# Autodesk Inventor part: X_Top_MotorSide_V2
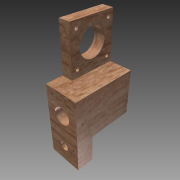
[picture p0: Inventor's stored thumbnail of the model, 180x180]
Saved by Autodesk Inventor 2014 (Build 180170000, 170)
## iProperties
Created: 2013-12
Part Number: X_Top_MotorSide_V2
Material: Birch
Document SubType Name: Modeling
Designer: Bram
Density: 0.512 g/cm^3
Appearance: Birch - Natural Medium Gloss
Author: Bram
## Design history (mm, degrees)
sketch "Sketch1"
  geometry: L1 (0, 0)-(30, 0); L2 (30, 0)-(30, 107); L3 (30, 107)-(0, 107); L4 (0, 107)-(0, 0); L5 (0, 107)-(20, 107); L6 (20, 107)-(20, 65); L7 (20, 65)-(0, 65); L8 (0, 65)-(0, 107); C1 r 4 at (15, 15); C2 r 7.5 at (15, 45)
  constraints: 16 end point, 4 parallel, 2 centre point, 2 horizontal, 2 perpendicular
  dimensions: "d0" = 30 distance of L3.end L2.end; "d1" = 107 distance of L2.end L1.end; "d2" = 20 distance of L6.end L7.end; "d3" = 42 distance of L5.end L6.end; "d6" = 8 diameter of C1; "d7" = 15 diameter of C2
extrude "Extrusion1" new body sketch "Sketch1" distance "d8" = 55; taper "d9" = 0 deg
sketch "Sketch3"
  geometry: L1 (-42, 0)-(0, 0); L2 (0, 0)-(0, 15); L3 (0, 15)-(-42, 15); L4 (-42, 15)-(-42, 0); C1 r 12 at (-22, 35); C2 r 1.5 at (-36.5, 50.5); C3 r 1.5 at (-6.5, 50.5); C4 r 1.5 at (-6.5, 20.5); C5 r 1.5 at (-36.5, 20.5); 1 further point
  constraints: 8 end point, 5 centre point, 2 parallel, 1 horizontal, 1 perpendicular
  dimensions: "d12" = 24 diameter of C1; "d18" = 3 diameter of C2; "d19" = 3 diameter of C3; "d20" = 3 diameter of C4; "d21" = 3 diameter of C5; "d22" = 42 distance of L3.end L2.end; "d23" = 15 distance of L2.end L1.end
extrude "Extrusion2" cut sketch "Sketch3" distance "d24" = 55; taper "d25" = 0 deg
sketch "Sketch4"
  geometry: L1 (65, 55)-(40, 55); L2 (40, 55)-(40, 15); L3 (40, 15)-(65, 15); L4 (65, 15)-(65, 55)
  constraints: 8 end point, 2 parallel, 1 horizontal, 1 perpendicular
  dimensions: "d26" = 25 distance of L3.end L2.end; "d27" = 40 distance of L2.end L1.end
extrude "Extrusion3" cut sketch "Sketch4" distance "d28" = 55; taper "d29" = 0 deg
body "Solid1"
